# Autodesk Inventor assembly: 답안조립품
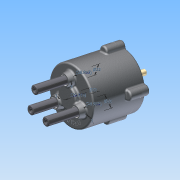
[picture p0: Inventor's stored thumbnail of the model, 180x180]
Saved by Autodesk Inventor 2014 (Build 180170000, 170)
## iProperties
Created: 2015-09
Part Number: 답안조립품
Document SubType Name: Assembly
Designer: study
Mass: 2160.28 g
Surface Area: 1801.23 cm^2
Volume: 438.526 cm^3
Density: 4.92622 g/cm^3
Author: study
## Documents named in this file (14)
- C:\Users\study\Desktop\350916V1001\답안조립품.iam
- C:\Users\study\Desktop\350916V1001\몸체.ipt
- C:\Users\study\Desktop\350916V1001\11-가변스프링.ipt
- C:\Users\study\Desktop\350916V1001\12-가변스프링.ipt
- C:\Users\study\Desktop\350916V1001\13-가변스프링.ipt
- C:\Users\study\Desktop\350916V1001\M5x0.8x20.ipt
- C:\Users\study\Desktop\350916V1001\멈춤링 10 x 1.ipt
- C:\Users\study\Desktop\350916V1001\멈춤링 22 x 1.2.ipt
- C:\Users\study\Desktop\350916V1001\메인 축.ipt
- C:\Users\study\Desktop\350916V1001\베어링 NA 4900.ipt
- C:\Users\study\Desktop\350916V1001\슬라이드 축.ipt
- C:\Users\study\Desktop\350916V1001\오일실.ipt
- C:\Users\study\Desktop\350916V1001\커버.ipt
- C:\Users\study\Desktop\350916V1001\판캠.ipt
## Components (7 placed, 4 different names)
1. 11-가변스프링:1
2. 13-가변스프링:1
3. 12-가변스프링:1
4. M5x0.8x20:1
5. M5x0.8x20:2
6. M5x0.8x20:3
7. M5x0.8x20:4
